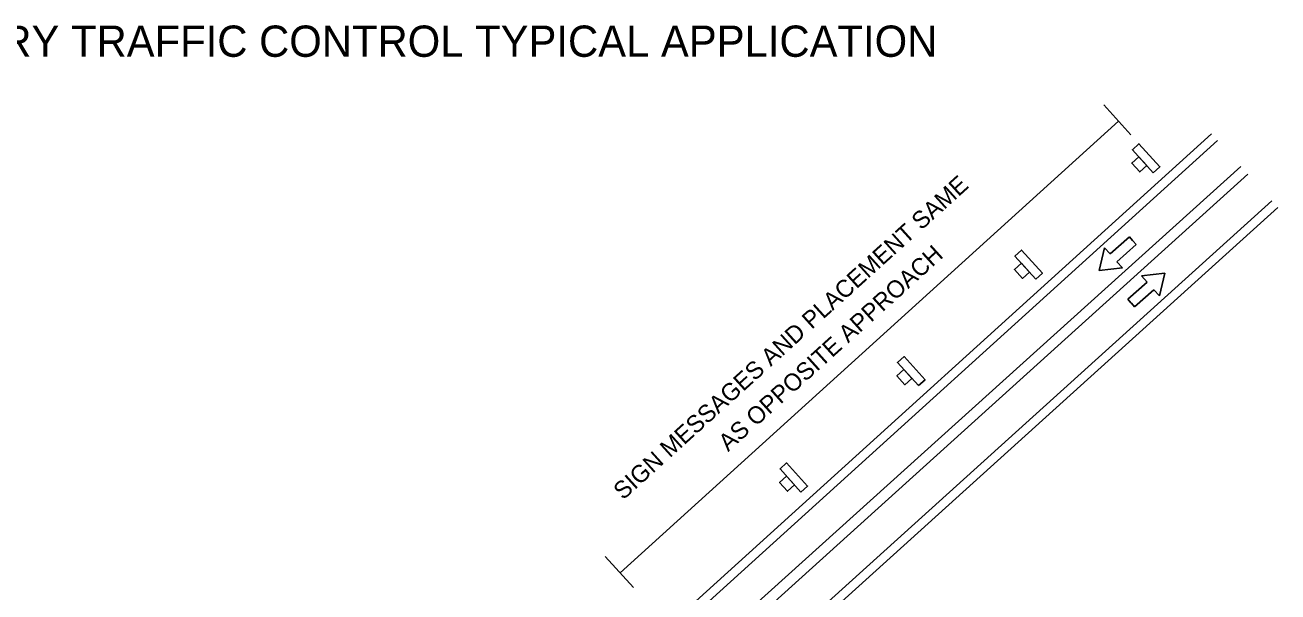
# Model space of a CAD drawing. Extents: x 1531.4 to 1538.6, y 1529.6 to 1539.7.
# Drawn here: x 1533.844 to 1538.193, y 1537.771 to 1539.738 of the extents above; entities that cross this region are included whole.
import ezdxf

# ---------------------------------------------------------------- set-up
doc = ezdxf.new("R2010")
doc.units = 0
for name, color, linetype in [('DETL-DIMS', 7, 'Continuous'), ('DETL-LINE', 7, 'Continuous'), ('DETL-NOTE', 7, 'Continuous'), ('DETL-TITL', 7, 'Continuous'), ('USER-BORD', 7, 'Continuous')]:
    doc.layers.add(name, color=color, linetype=linetype)

# ---------------------------------------------------------------- blocks, each defined once
blk = doc.blocks.new('DIR4')
at = {"layer": 'USER-BORD'}
for p, q in [((0, 0.0012), (-0.0342, -0.0477)), ((0, 0.0012), (0.0342, -0.0477)), ((-0.0342, -0.0477), (-0.0132, -0.0477)), ((-0.0132, -0.1133), (-0.0132, -0.0477)), ((0.0342, -0.0477), (0.0132, -0.0477)), ((0.0132, -0.1133), (0.0132, -0.0477)), ((-0.0011, -0.1133), (-0.0132, -0.1133)), ((-0.0011, -0.1133), (0.0011, -0.1133)), ((0.0011, -0.1133), (0.0132, -0.1133))]:
    blk.add_line(p, q, dxfattribs=at)

msp = doc.modelspace()

# ---------------------------------------------------------------- linework, layer by layer
at = {"layer": 'DETL-DIMS'}
for p, q in [((1537.6826, 1539.3574), (1537.5892, 1539.4605)), ((1535.9556, 1537.787), (1535.8583, 1537.8943))]:
    msp.add_line(p, q, dxfattribs=at)
msp.add_lwpolyline([(1535.9101, 1537.8372), (1537.6403, 1539.4041)], dxfattribs=at)
at = {"layer": 'DETL-LINE'}
for p, q in [((1536.0895, 1537.6646), (1537.9623, 1539.3605)), ((1536.1102, 1537.6414), (1537.9832, 1539.3374)), ((1534.7936, 1536.3), (1538.0646, 1539.2471)), ((1535.4388, 1536.8288), (1538.0887, 1539.2203)), ((1535.2575, 1536.4968), (1538.1724, 1539.1276)), ((1535.5433, 1536.713), (1538.1933, 1539.1044))]:
    msp.add_line(p, q, dxfattribs=at)
for points in [[(1537.7605, 1539.2253), (1537.7834, 1539.246), (1537.7108, 1539.3262), (1537.6879, 1539.3055)], [(1537.738, 1539.2502), (1537.7103, 1539.2808), (1537.686, 1539.2588), (1537.7137, 1539.2282)], [(1537.3529, 1538.8561), (1537.3758, 1538.8768), (1537.3031, 1538.957), (1537.2802, 1538.9363)], [(1537.3303, 1538.881), (1537.3026, 1538.9116), (1537.2783, 1538.8897), (1537.3061, 1538.859)], [(1536.9452, 1538.4869), (1536.9681, 1538.5076), (1536.8955, 1538.5878), (1536.8726, 1538.5671)], [(1536.9226, 1538.5118), (1536.8949, 1538.5424), (1536.8707, 1538.5205), (1536.8984, 1538.4899)], [(1536.5375, 1538.1177), (1536.5604, 1538.1385), (1536.4878, 1538.2187), (1536.4649, 1538.1979)], [(1536.5149, 1538.1426), (1536.4872, 1538.1732), (1536.463, 1538.1513), (1536.4907, 1538.1207)]]:
    msp.add_lwpolyline(points, close=True, dxfattribs=at)

# ---------------------------------------------------------------- block references
at = {"layer": 'DETL-LINE', "xscale": 1.3628340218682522}
for p, yscale, rotation in [((1537.574, 1538.8872), -1.362834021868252, -48.483795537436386), ((1537.7994, 1538.8759), 1.3628340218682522, -48.48379553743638)]:
    msp.add_blockref('DIR4', p, dxfattribs=dict(at, yscale=yscale, rotation=rotation))

# ---------------------------------------------------------------- texts
at = {"layer": 'DETL-NOTE'}
for s, p in [('SIGN MESSAGES AND PLACEMENT SAME', (1535.9201, 1538.0879)), (' AS OPPOSITE APPROACH', (1536.2682, 1538.241))]:
    msp.add_text(s, height=0.06, rotation=42.1252, dxfattribs=at).set_placement(p)
at = {"layer": 'DETL-TITL'}
msp.add_text('TEMPORARY TRAFFIC CONTROL TYPICAL APPLICATION', height=0.10852, dxfattribs=at).set_placement((1533.044, 1539.6276))

doc.saveas('drawing.dxf')
